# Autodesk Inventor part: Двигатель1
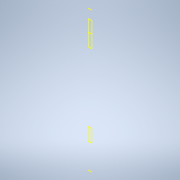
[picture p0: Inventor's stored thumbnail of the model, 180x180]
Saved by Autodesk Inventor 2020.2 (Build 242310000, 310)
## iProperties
Created: 2020-04
Part Number: Двигатель1
Material: Типовые
Document SubType Name: Modeling
Designer: Алексей
Density: 1 g/cm^3
Appearance: По умолчанию
Author: Алексей
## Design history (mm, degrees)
sketch "Эскиз1"
  geometry: L1 (0, 13)-(0, 0) reference; L2 (0, 0)-(4, 0) reference; L3 (4, 13)-(4, 0) reference; L4 (0, 13)-(4, 13) reference; L5 (0, 0)-(0, -14) reference; L6 (0, -14)-(4, -14) reference; L7 (4, 0)-(4, -14) reference; L8 (0, 0)-(4, 0) reference; L9 (0, -91)-(0, -105) reference; L10 (0, -105)-(4, -105) reference; L11 (4, -91)-(4, -105) reference; L12 (0, -91)-(4, -91) reference; L13 (0, 23)-(4, 23) reference; L14 (0, -133)-(4, -133) reference
  constraints: 1 other
  node "Ссылка1"
  node "Ссылка2"
  node "Ссылка3"
  node "Ссылка4"
  node "Ссылка5"
